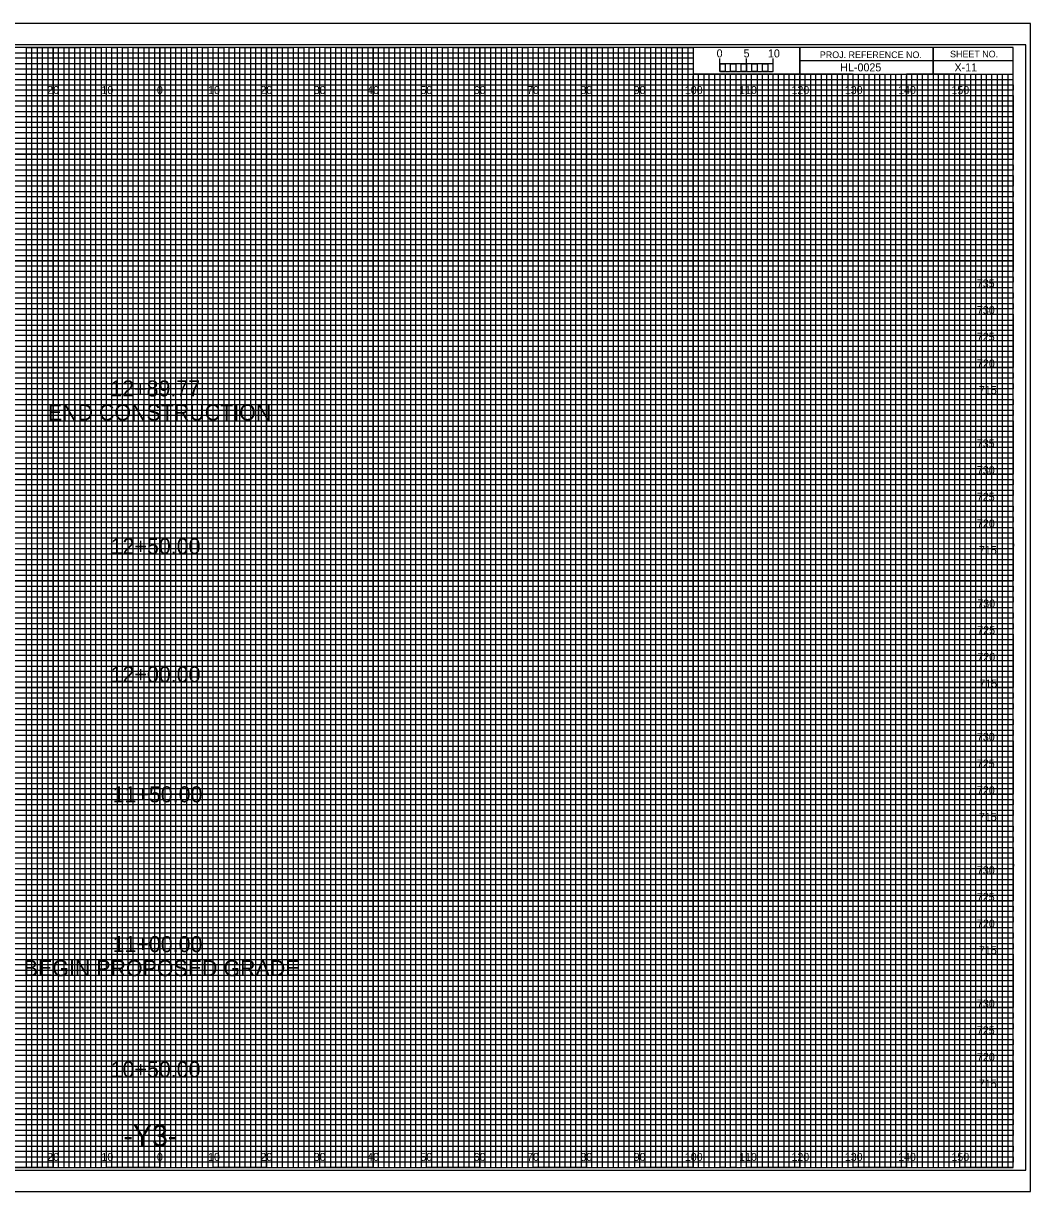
# Model space of a CAD drawing. Extents: x -13 to 323, y -5 to 434.
# Drawn here: x 134.4 to 323.3, y -4.5 to 214.5 of the extents above; entities that cross this region are included whole.
import ezdxf

# ---------------------------------------------------------------- set-up
doc = ezdxf.new("R2010")
doc.units = 0
for name, color, linetype in [('Prop XS Alignment Label', 7, 'Continuous'), ('Prop XS Bar Scale Labels', 7, 'Continuous'), ('Prop XS Elevation Labels', 7, 'Continuous'), ('Prop XS Offset Labels', 7, 'Continuous'), ('Prop XS Project Number', 7, 'Continuous'), ('Prop XS Sheet Number', 7, 'Continuous'), ('Prop XS Station Labels', 7, 'Continuous'), ('Sheet Cross Section CELL', 7, 'Continuous'), ('Sheet Cross Section Grid Major CELL', 7, 'Continuous'), ('Sheet Cross Section Grid Middle CELL', 7, 'Continuous'), ('Sheet Cross Section Grid Minor 1 CELL', 7, 'Continuous'), ('Sheet Cross Section Grid Minor 2 CELL', 7, 'Continuous'), ('Sheet Cross Section Scale CELL', 7, 'Continuous'), ('Sheet Cutting Line CELL', 7, 'Continuous'), ('Sheet DOT Grid CELL', 7, 'Continuous'), ('Sheet Plot Border Inside CELL', 7, 'Continuous'), ('Sheet Plot Border Outside CELL', 7, 'Continuous')]:
    doc.layers.add(name, color=color, linetype=linetype)

msp = doc.modelspace()

# ---------------------------------------------------------------- linework, layer by layer
at = {"layer": 'Sheet Cross Section CELL'}
for p, q in [((305, 210), (305, 205)), ((305, 205), (305, 210)), ((280, 207.5), (280, 205)), ((320, 207.49), (280, 207.49)), ((280, 205), (320, 205))]:
    msp.add_line(p, q, dxfattribs=at)
for points in [[(320, 210), (0, 210), (0, 0), (320, 0)], [(280, 210), (260, 210), (260, 205.03), (280, 205.03)], [(320, 210), (280, 210), (280, 205), (320, 205)]]:
    msp.add_lwpolyline(points, close=True, dxfattribs=at)
at = {"layer": 'Sheet Cross Section Grid Major CELL'}
for p, q in [((150, 210), (140, 210)), ((140, 210), (140, 0)), ((150, 0), (150, 210)), ((170, 210), (160, 210)), ((160, 210), (160, 0)), ((170, 0), (170, 210)), ((190, 210), (180, 210)), ((180, 210), (180, 0)), ((190, 0), (190, 210)), ((210, 210), (200, 210)), ((200, 210), (200, 0)), ((210, 0), (210, 210)), ((230, 210), (220, 210)), ((220, 210), (220, 0)), ((230, 0), (230, 210)), ((250, 210), (240, 210)), ((240, 210), (240, 0)), ((250, 0), (250, 210)), ((260, 210), (260, 0)), ((270, 0), (270, 205)), ((290, 205), (280, 205)), ((280, 205), (280, 0)), ((290, 0), (290, 205)), ((310, 205), (300, 205)), ((300, 205), (300, 0)), ((310, 0), (310, 205)), ((140, 0), (130, 0)), ((160, 0), (150, 0)), ((180, 0), (170, 0)), ((200, 0), (190, 0)), ((220, 0), (210, 0)), ((240, 0), (230, 0)), ((260, 0), (250, 0)), ((280, 0), (270, 0)), ((300, 0), (290, 0)), ((320, 0), (310, 0)), ((320, 0), (320, 0))]:
    msp.add_line(p, q, dxfattribs=at)
for points in [[(0, 200), (320, 200), (320, 190), (0, 190)], [(0, 180), (320, 180), (320, 170), (0, 170)], [(0, 160), (320, 160), (320, 150), (0, 150)], [(0, 140), (320, 140), (320, 130), (0, 130)], [(0, 120), (320, 120), (320, 110), (0, 110)], [(0, 100), (320, 100), (320, 90), (0, 90)], [(0, 80), (320, 80), (320, 70), (0, 70)], [(0, 60), (320, 60), (320, 50), (0, 50)], [(0, 40), (320, 40), (320, 30), (0, 30)], [(0, 20), (320, 20), (320, 10), (0, 10)]]:
    msp.add_lwpolyline(points, dxfattribs=at)
at = {"layer": 'Sheet Cross Section Grid Middle CELL'}
for points in [[(125, 0), (135, 0), (135, 210), (145, 210), (145, 0), (155, 0), (155, 210), (165, 210), (165, 0), (175, 0), (175, 210), (185, 210), (185, 0), (195, 0), (195, 210), (205, 210), (205, 0), (215, 0), (215, 210), (225, 210), (225, 0), (235, 0), (235, 210), (245, 210), (245, 0), (255, 0), (255, 210), (259.93, 210), (260, 210), (260, 205), (264.99, 205), (264.99, 0), (275, 0), (275, 205), (285, 205), (285, 0), (295, 0), (295, 205), (305, 205), (305, 0), (315, 0), (315, 205)], [(0, 205), (275, 205)], [(0, 185), (320, 185), (320, 195), (0, 195)], [(0, 165), (320, 165), (320, 175), (0, 175)], [(0, 145), (320, 145), (320, 155), (0, 155)], [(0, 125), (320, 125), (320, 135), (0, 135)], [(0, 105), (320, 105), (320, 115), (0, 115)], [(0, 85), (320, 85), (320, 95), (0, 95)], [(0, 65), (320, 65), (320, 75), (0, 75)], [(0, 45), (320, 45), (320, 55), (0, 55)], [(0, 25), (320, 25), (320, 35), (0, 35)], [(0, 5), (320, 5), (320, 15), (0, 15)]]:
    msp.add_lwpolyline(points, dxfattribs=at)
at = {"layer": 'Sheet Cross Section Grid Minor 1 CELL'}
for p, q in [((0, 209), (260, 209)), ((260, 209), (260, 207.98)), ((260, 207.98), (0, 207.98)), ((0, 207), (260, 207)), ((260, 205.89), (0, 205.89)), ((260, 207), (260, 205.89)), ((0, 204), (320, 204))]:
    msp.add_line(p, q, dxfattribs=at)
for points in [[(0, 203), (270, 203), (320, 203), (320, 202), (0, 202)], [(0, 201), (320, 201), (320, 199), (0, 199)], [(0, 198), (320, 198), (320, 197), (0, 196.98)], [(0, 196), (320, 196), (320, 194), (0, 194)], [(0, 193), (320, 193), (320, 192), (0, 192)], [(0, 191), (320, 191), (320, 189), (0, 189)], [(0, 188), (320, 188), (320, 187), (0, 187)], [(0, 186), (320, 186), (320, 184), (0, 184)], [(0, 183), (320, 183), (320, 182), (0, 182)], [(0, 181), (320, 181), (320, 179), (0, 179)], [(0, 178), (320, 178), (320, 177), (0, 177)], [(0, 176), (320, 176), (320, 173.95), (320, 173), (320, 172), (0, 172)], [(0, 174), (320, 174), (320, 173), (0, 173)], [(0, 171), (320, 171), (320, 169), (0, 169.03)], [(0, 169.03), (320, 169), (320, 168), (0, 168)], [(0, 167), (320, 167), (320, 166), (0, 166)], [(0, 164), (320, 164), (320, 163), (0, 163)], [(0, 162), (320, 162), (320, 161), (0, 161)], [(-0.07, 158.89), (320, 158.89), (320, 157.88), (-0.07, 157.88)], [(0, 157), (320, 157), (320, 156), (0, 156)], [(0, 154), (320, 154), (320, 153), (0, 153)], [(0, 152), (320, 152), (320, 151), (0, 151)], [(0, 149), (320, 149), (320, 148), (0, 148)], [(0, 147), (320, 147), (320, 146), (0, 146)], [(0, 144), (320, 144), (320, 143), (0, 143)], [(0, 142), (320, 142), (320, 141), (0, 141)], [(0, 139), (320, 139), (319.99, 137.98), (0, 138)], [(0, 137), (320, 137), (320, 136), (0, 136)], [(0, 134), (320, 134), (320, 133), (0, 133)], [(0, 132), (320, 132), (320, 131), (0, 131)], [(0, 129), (320, 129), (320, 128), (0, 128)], [(0, 127), (320, 127), (320, 126), (0, 126)], [(0, 124), (320, 124), (320, 123), (0, 123)], [(0, 122), (320, 122), (320, 121), (0, 121)], [(0, 119), (320, 119), (320, 118), (0, 118)], [(0, 116.99), (320.07, 116.91), (320, 116), (0, 116)], [(0, 114), (320, 114), (320, 113), (0, 113)], [(0, 112), (320, 112), (320, 111), (0, 111)], [(0, 109), (320, 109), (320, 108), (0, 108)], [(0, 107), (320, 107), (320, 106), (0, 106)], [(0, 104), (320, 104), (320, 103), (0, 103)], [(0, 102), (320, 102), (320, 101), (0, 101)], [(0, 99), (320, 99), (320, 98), (0, 98)], [(0, 97), (320, 97), (320, 96), (0, 96)], [(0, 94), (320, 94), (320, 93), (0, 93)], [(0, 92), (320, 92), (320, 91), (0, 91)], [(0, 89), (320, 89), (320, 88), (0, 88)], [(0, 87), (320, 87), (320, 86), (0, 86)], [(0, 84), (320, 84), (320, 83), (0, 83)], [(0, 82), (320, 82), (320, 81), (0, 81)], [(0, 79), (320, 79), (319.99, 77.98), (0, 78)], [(0, 77), (320, 77), (320, 76), (0, 76)], [(0, 74), (320, 74), (320, 73), (0, 73)], [(0, 72), (320, 72), (320, 71), (0, 71)], [(0, 69), (320, 69), (320, 68), (0, 68)], [(0, 67), (320, 67), (320, 66), (0, 66)], [(0, 64), (320, 64), (320, 63), (0, 63)], [(0, 62), (320, 62), (320, 61), (0, 61)], [(0, 59), (320, 59), (320, 58), (0, 58)], [(0, 56.99), (320.07, 56.91), (320, 56), (0, 56)], [(0, 54), (320, 54), (320, 53), (0, 53)], [(0, 52), (320, 52), (320, 51), (0, 51)], [(0, 49), (320, 49), (320, 48), (0, 48)], [(0, 47), (320, 47), (320, 46), (0, 46)], [(0, 44), (320, 44), (320, 43), (0, 43)], [(0, 42), (320, 42), (320, 41), (0, 41)], [(0, 39), (320, 39), (320, 38), (0, 38)], [(0, 37), (320, 37), (320, 36), (0, 36)], [(0, 34), (320, 34), (320, 33), (0, 33)], [(0, 32), (320, 32), (320, 31), (0, 31)], [(0, 29), (320, 29), (320, 28), (0, 28)], [(0, 27), (320, 27), (320, 26), (0, 26)], [(0, 24), (320, 24), (320, 23), (0, 23)], [(0, 22), (320, 22), (320, 21), (0, 21)], [(0, 19), (320, 19), (320, 18), (0, 18)], [(0, 17), (320, 17), (320, 16), (0, 16)], [(0, 14), (320, 14), (320, 13), (0, 13)], [(0, 12), (320, 12), (320, 11), (0, 11)], [(0, 9), (320, 9), (320, 8), (0, 8)], [(0, 7), (320, 7), (320, 6), (0, 6)], [(0, 4), (320, 4), (320, 3), (0, 3)], [(0, 2), (320, 2), (320, 1), (0, 1)]]:
    msp.add_lwpolyline(points, dxfattribs=at)
at = {"layer": 'Sheet Cross Section Grid Minor 2 CELL'}
for p, q in [((267, 205), (266.01, 205)), ((266.01, 205), (266.01, 0)), ((267, 0), (267, 205)), ((269, 205), (268, 205)), ((268, 205), (268, 0)), ((269, 0), (269, 205)), ((266.01, 0), (265, 0)), ((268, 0), (267, 0))]:
    msp.add_line(p, q, dxfattribs=at)
for points in [[(135, 0), (136, 0), (136, 210), (137, 210), (137, 0)], [(137, 0), (138, 0), (138, 210), (139, 210), (139, 0)], [(140, 0), (141, 0), (141, 210), (142, 210), (142, 0)], [(142, 0), (143, 0), (143, 210), (144, 210), (144, 0)], [(145, 0), (146, 0), (146, 210), (147, 210), (147, 0)], [(147, 0), (148, 0), (148, 210), (149, 210), (149, 0)], [(150, 0), (151, 0), (151, 210), (152, 210), (152, 0)], [(152, 0), (153, 0), (153, 210), (154, 210), (154, 0)], [(155, 0), (156, 0), (156, 210), (157, 210), (157, 0)], [(157, 0), (158, 0), (158, 210), (159, 210), (159, 0)], [(160, 0), (161, 0), (161, 210), (162, 210), (162, 0)], [(162, 0), (163, 0), (163, 210), (164, 210), (164, 0)], [(165, 0), (166, 0), (166, 210), (167, 210), (167, 0)], [(167, 0), (168, 0), (168, 210), (169, 210), (169, 0)], [(170, 0), (171, 0), (171, 210), (172, 210), (172, 0)], [(172, 0), (173, 0), (173, 210), (174, 210), (174, 0)], [(175, 0), (176, 0), (176, 210), (177, 210), (177, 0)], [(177, 0), (178, 0), (178, 210), (179, 210), (179, 0)], [(180, 0), (181, 0), (181, 210), (182, 210), (182, 0)], [(182, 0), (183, 0), (183, 210), (184, 210), (184, 0)], [(185, 0), (186, 0), (186, 210), (187, 210), (187, 0)], [(187, 0), (188, 0), (188, 210), (189, 210), (189, 0)], [(190, 0), (191, 0), (191, 210), (192, 210), (192, 0)], [(192, 0), (193, 0), (193, 210), (194, 210), (194, 0)], [(195, 0), (196, 0), (196, 210), (197, 210), (197, 0)], [(197, 0), (198, 0), (198, 210), (199, 210), (199, 0)], [(200, 0), (201, 0), (201, 210), (202, 210), (202, 0)], [(202, 0), (203, 0), (203, 210), (204, 210), (204, 0)], [(205, 0), (206, 0), (206, 210), (207, 210), (207, 0)], [(207, 0), (208, 0), (208, 210), (209, 210), (209, 0)], [(210, 0), (211, 0), (211, 210), (212, 210), (212, 0)], [(212, 0), (213, 0), (213, 210), (214, 210), (214, 0)], [(215, 0), (216, 0), (216, 210), (217, 210), (217, 0)], [(217, 0), (218, 0), (218, 210), (219, 210), (219, 0)], [(220, 0), (221, 0), (221, 210), (222, 210), (222, 0)], [(222, 0), (223, 0), (223, 210), (224, 210), (224, 0)], [(225, 0), (226, 0), (226, 210), (227, 210), (227, 0)], [(227, 0), (228, 0), (228, 210), (229, 210), (229, 0)], [(230, 0), (231, 0), (231, 210), (232, 210), (232, 0)], [(232, 0), (233, 0), (233, 210), (234, 210), (234, 0)], [(235, 0), (236, 0), (236, 210), (237, 210), (237, 0)], [(237, 0), (238, 0), (238, 210), (239, 210), (239, 0)], [(240, 0), (241, 0), (241, 210), (242, 210), (242, 0)], [(242, 0), (243, 0), (243, 210), (244, 210), (244, 0)], [(245, 0), (246, 0), (246, 210), (247, 210), (247, 0)], [(247, 0), (248, 0), (248, 210), (249, 210), (249, 0)], [(250, 0), (251, 0), (251, 210), (252, 210), (252, 0)], [(252, 0), (253, 0), (253, 210), (254, 210), (254, 0)], [(255, 0), (256, 0), (256, 210), (257, 210), (257, 0)], [(257, 0), (258, 0), (258, 210), (259, 210), (259, 0)], [(260, 0), (261, 0), (261, 205), (262.02, 205), (262.02, 0)], [(262, 0), (263, 0), (263, 205), (263.99, 205), (263.99, 0)], [(270, 0), (270.98, 0), (270.98, 205), (272, 205), (272, 0)], [(272, 0), (273, 0), (273, 205), (274.05, 205), (274.05, 0)], [(275, 0), (276, 0), (276, 205), (277, 205), (277, 0)], [(277, 0), (278, 0), (278, 205), (279, 205), (279, 0)], [(280, 0), (281, 0), (281, 205), (282, 205), (282, 0)], [(282, 0), (283, 0), (283, 205), (284, 205), (284, 0)], [(285, 0), (286, 0), (286, 205), (287, 205), (287, 0)], [(287, 0), (288, 0), (288, 205), (289, 205), (289, 0)], [(290, 0), (291, 0), (291, 205), (292, 205), (292, 0)], [(292, 0), (293, 0), (293, 205), (294, 205), (294, 0)], [(295, 0), (296, 0), (296, 205), (297, 205), (297, 0)], [(297, 0), (298, 0), (298, 205), (299, 205), (299, 0)], [(300, 0), (301, 0), (301, 205), (302, 205), (302, 0)], [(302, 0), (303, 0), (303, 205), (304, 205), (304, 0)], [(305, 0), (306, 0), (306, 205), (307, 205), (307, 0)], [(307, 0), (308, 0), (308, 205), (309, 205), (309, 0)], [(310, 0), (311, 0), (311, 205), (312, 205), (312, 0)], [(312, 0), (313, 0), (313, 205), (314, 205), (314, 0)], [(315, 0), (316, 0), (316, 205), (317, 205), (317, 0)], [(317, 0), (318, 0), (318, 205), (319, 205), (319, 0)]]:
    msp.add_lwpolyline(points, dxfattribs=at)
at = {"layer": 'Sheet Cross Section Scale CELL'}
for p, q in [((265, 205.49), (265, 207.9)), ((265, 206.9), (265, 207.9)), ((270, 205.49), (270, 207.9)), ((275, 205.49), (275, 207.9)), ((275, 206.9), (275, 207.9))]:
    msp.add_line(p, q, dxfattribs=at)
for points in [[(275, 206.9), (265, 206.9), (265, 205.49), (275, 205.49)], [(265, 206.9), (266, 206.9), (266, 205.49), (265, 205.49)], [(267, 206.9), (268, 206.9), (268, 205.49), (267, 205.49)], [(269, 206.9), (270, 206.9), (270, 205.49), (269, 205.49)], [(271, 206.9), (272, 206.9), (272, 205.49), (271, 205.49)], [(273, 206.9), (274, 206.9), (274, 205.49), (273, 205.49)]]:
    msp.add_lwpolyline(points, close=True, dxfattribs=at)
at = {"layer": 'Sheet Cutting Line CELL'}
for p, q in [((323.3, 214.5), (-13.4, 214.5)), ((-13.4, -4.5), (323.3, -4.5))]:
    msp.add_line(p, q, dxfattribs=at)
at = {"layer": 'Sheet DOT Grid CELL'}
for p, q in [((140, 0), (140, 210)), ((150, 0), (150, 210)), ((160, 0), (160, 210)), ((170, 0), (170, 210)), ((180, 0), (180, 210)), ((190, 0), (190, 210)), ((200, 0), (200, 210)), ((210, 0), (210, 210)), ((220, 0), (220, 210)), ((230, 0), (230, 210)), ((240, 0), (240, 210)), ((250, 0), (250, 210)), ((260, 0), (260, 204.69)), ((270, 0), (270, 204.69)), ((280, 0), (280, 204.69)), ((290, 0), (290, 204.69)), ((300, 0), (300, 204.69)), ((310, 0), (310, 204.69)), ((0, 200), (320, 200)), ((0, 190), (320, 190)), ((0, 180), (320, 180)), ((0, 170), (320, 170)), ((0, 160), (320, 160)), ((0, 150), (320, 150)), ((0, 140), (320, 140)), ((0, 130), (320, 130)), ((0, 120), (320, 120)), ((0, 110), (320, 110)), ((0, 100), (320, 100)), ((0, 90), (320, 90)), ((0, 80), (320, 80)), ((0, 70), (320, 70)), ((0, 60), (320, 60)), ((0, 50), (320, 50)), ((0, 40), (320, 40)), ((0, 30), (320, 30)), ((0, 20), (320, 20)), ((0, 10), (320, 10))]:
    msp.add_line(p, q, dxfattribs=at)
at = {"layer": 'Sheet Plot Border Inside CELL'}
msp.add_lwpolyline([(-10.8, -0.5), (322.4, -0.5), (322.4, 210.5), (-10.8, 210.5)], close=True, dxfattribs=at)
at = {"layer": 'Sheet Plot Border Outside CELL'}
msp.add_lwpolyline([(-13.4, -4.5), (323.3, -4.5), (323.3, 214.5), (-13.4, 214.5)], close=True, dxfattribs=at)

# ---------------------------------------------------------------- texts
at = {"layer": 'Prop XS Alignment Label'}
msp.add_text('-Y3-', height=4, dxfattribs=at).set_placement((153.17, 4))
at = {"layer": 'Prop XS Bar Scale Labels'}
for s, p in [('5', (269.47, 208.12)), ('10', (274.04, 208.12))]:
    msp.add_text(s, height=1.5, dxfattribs=at).set_placement(p)
at = {"layer": 'Prop XS Elevation Labels'}
for s, p in [('735', (313.2, 165)), ('730', (313.22, 160)), ('725', (313.21, 155)), ('720', (313.23, 150)), ('715', (313.59, 145)), ('735', (313.2, 135)), ('730', (313.22, 130)), ('725', (313.21, 125)), ('720', (313.23, 120)), ('715', (313.59, 115)), ('730', (313.3, 105)), ('725', (313.29, 100)), ('720', (313.31, 95)), ('715', (313.67, 90)), ('730', (313.22, 80)), ('725', (313.21, 75)), ('720', (313.23, 70)), ('715', (313.59, 65)), ('730', (313.22, 55)), ('725', (313.21, 50)), ('720', (313.23, 45)), ('715', (313.59, 40)), ('730', (313.22, 30)), ('725', (313.21, 25)), ('720', (313.23, 20)), ('715', (313.59, 15))]:
    msp.add_text(s, height=1.5, dxfattribs=at).set_placement(p)
at = {"layer": 'Prop XS Offset Labels'}
for s, p in [('20', (138.86, 201.25)), ('10', (149.04, 201.25)), ('0', (159.45, 201.25)), ('0', (159.45, 201.25)), ('10', (169.04, 201.25)), ('20', (178.86, 201.25)), ('30', (188.86, 201.25)), ('40', (198.86, 201.25)), ('50', (208.86, 201.25)), ('60', (218.86, 201.25)), ('70', (228.86, 201.25)), ('80', (238.86, 201.25)), ('90', (248.86, 201.25)), ('100', (258.44, 201.25)), ('110', (268.62, 201.25)), ('120', (278.44, 201.25)), ('130', (288.44, 201.25)), ('140', (298.44, 201.25)), ('150', (308.44, 201.25)), ('20', (138.86, 1.25)), ('10', (149.04, 1.25)), ('0', (159.45, 1.25)), ('0', (159.45, 1.25)), ('10', (169.04, 1.25)), ('20', (178.86, 1.25)), ('30', (188.86, 1.25)), ('40', (198.86, 1.25)), ('50', (208.86, 1.25)), ('60', (218.86, 1.25)), ('70', (228.86, 1.25)), ('80', (238.86, 1.25)), ('90', (248.86, 1.25)), ('100', (258.44, 1.25)), ('110', (268.62, 1.25)), ('120', (278.44, 1.25)), ('130', (288.44, 1.25)), ('140', (298.44, 1.25)), ('150', (308.44, 1.25))]:
    msp.add_text(s, height=1.5, dxfattribs=at).set_placement(p)
at = {"layer": 'Prop XS Project Number'}
msp.add_text('HL-0025', height=1.5, dxfattribs=at).set_placement((287.6, 205.5))
at = {"layer": 'Prop XS Sheet Number'}
msp.add_text('X-11', height=1.5, dxfattribs=at).set_placement((309.02, 205.5))
at = {"layer": 'Prop XS Station Labels'}
for s, p in [('12+89.77', (150.7, 144.57)), ('END CONSTRUCTION', (138.99, 140.07)), ('12+50.00', (150.77, 115)), ('12+00.00', (150.77, 90.97)), ('11+50.00', (151.13, 68.48)), ('11+00.00', (151.13, 40.4)), ('BEGIN PROPOSED GRADE', (134.47, 35.9)), ('10+50.00', (150.77, 16.92))]:
    msp.add_text(s, height=3, dxfattribs=at).set_placement(p)
at = {"layer": 'Sheet Cross Section CELL'}
for s, p in [('PROJ. REFERENCE NO.', (283.77, 207.99)), ('SHEET NO.', (308.19, 208.12))]:
    msp.add_text(s, height=1.25, dxfattribs=at).set_placement(p)
at = {"layer": 'Sheet Cross Section Scale CELL'}
msp.add_text('0', height=1.5, dxfattribs=at).set_placement((264.41, 208.12))

doc.saveas('drawing.dxf')
